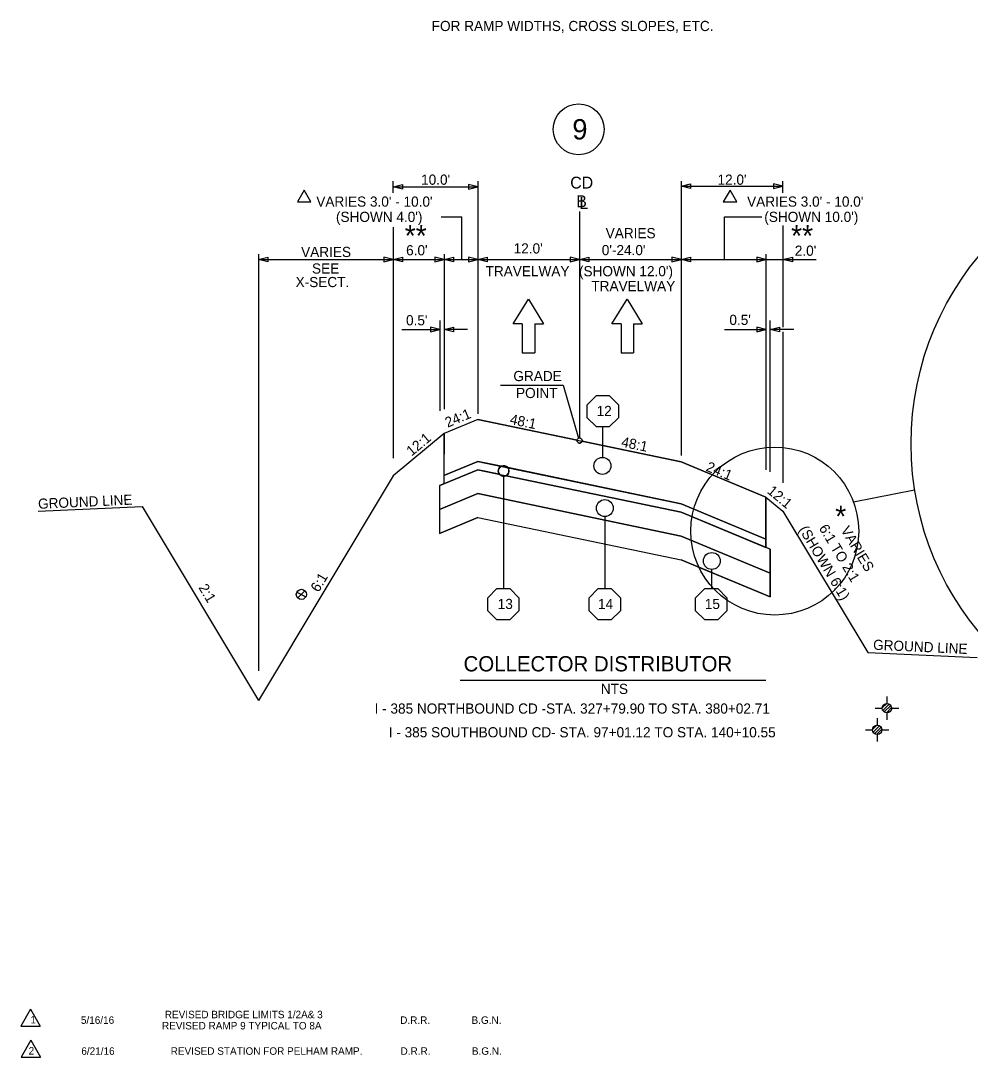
# Model space of a CAD drawing. Extents: x 5017 to 5774, y 4942 to 5266.
# Drawn here: x 5017.3 to 5129.3, y 5018.6 to 5140.9 of the extents above; entities that cross this region are included whole.
import ezdxf

# ---------------------------------------------------------------- set-up
doc = ezdxf.new("R2010")
doc.units = 0
for name, color, linetype in [('Level 20', 7, 'Continuous'), ('Level 25', 7, 'Continuous'), ('NotForConst', 7, 'Continuous'), ('RD_EX_SU_TX_Misc', 7, 'Continuous'), ('RD_QTY_Miscl_1', 7, 'Continuous'), ('RD_QTY_Miscl_2', 7, 'Continuous'), ('RD_QTY_Miscl_3', 7, 'Continuous'), ('RD_QTY_Stab_Agg_3', 7, 'Continuous'), ('RD_SHT_TX', 7, 'Continuous'), ('RD_SHT_Typical', 7, 'Continuous'), ('RD_TX_TypSect', 7, 'Continuous'), ('RD_XS_ExGround', 7, 'Continuous'), ('typical_on', 7, 'Continuous')]:
    doc.layers.add(name, color=color, linetype=linetype)

# ---------------------------------------------------------------- blocks, each defined once
blk = doc.blocks.new('SUE_TFP')
at = {"layer": 'RD_EX_SU_TX_Misc'}
for p, q in [((0, 5.5), (0, 2.22)), ((-2.21, 0.13), (-0.13, 2.21)), ((-1.96, -1.03), (1.03, 1.96)), ((-1.31, -1.79), (1.79, 1.31)), ((-0.3, -2.2), (2.2, 0.3)), ((2.22, 0), (5.53, 0.01)), ((-5.53, -0.01), (-2.22, 0)), ((0, -2.22), (0, -5.5))]:
    blk.add_line(p, q, dxfattribs=at)
blk.add_circle((0, 0), 2.22, dxfattribs=at)

msp = doc.modelspace()

# ---------------------------------------------------------------- linework, layer by layer
at = {"layer": 'Level 20'}
for p, q in [((5075.36, 5105.16), (5077.18, 5108.07)), ((5077.18, 5108.07), (5078.97, 5105.15)), ((5087.01, 5105.16), (5088.83, 5108.07)), ((5088.83, 5108.07), (5090.61, 5105.15)), ((5076.45, 5105.16), (5075.36, 5105.16)), ((5076.45, 5105.16), (5076.45, 5101.76)), ((5077.91, 5105.15), (5078.97, 5105.15)), ((5077.91, 5105.15), (5077.91, 5101.75)), ((5088.1, 5105.16), (5087.01, 5105.16)), ((5088.1, 5105.16), (5088.1, 5101.76)), ((5089.56, 5105.15), (5090.61, 5105.15)), ((5089.56, 5105.15), (5089.56, 5101.75)), ((5076.45, 5101.76), (5077.91, 5101.75)), ((5088.1, 5101.76), (5089.56, 5101.75))]:
    msp.add_line(p, q, dxfattribs=at)
at = {"layer": 'Level 25'}
msp.add_lwpolyline([(5073.89, 5097.92), (5081.29, 5097.92), (5083.09, 5091.66)], dxfattribs=at)
msp.add_circle((5083.1, 5128.12), 3, dxfattribs=at)
at = {"layer": 'RD_QTY_Miscl_1'}
for p, q in [((5071.21, 5088.93), (5067.2, 5087.26)), ((5073.97, 5088.36), (5071.21, 5088.93)), ((5067.19, 5086.28), (5071.19, 5087.95)), ((5071.19, 5087.95), (5073.74, 5087.42)), ((5095.21, 5083.93), (5074.73, 5088.2)), ((5074.55, 5087.25), (5095.21, 5082.94)), ((5105.21, 5079.77), (5095.21, 5083.93)), ((5095.21, 5082.94), (5105.21, 5078.78)), ((5105.21, 5078.78), (5105.21, 5079.77))]:
    msp.add_line(p, q, dxfattribs=at)
msp.add_lwpolyline([(5067.2, 5087.26), (5067.2, 5087.26), (5067.19, 5086.28)], dxfattribs=at)
for start, end in [(116.2833, 217.2732), (299.1906, 40.1805)]:
    msp.add_arc((5074.25, 5087.8), 0.63, start, end, dxfattribs=at)
at = {"layer": 'RD_QTY_Miscl_2'}
for p, q in [((5073.74, 5087.42), (5071.19, 5087.95)), ((5095.21, 5082.94), (5074.55, 5087.25)), ((5066.69, 5086.08), (5066.69, 5083.26)), ((5066.69, 5083.26), (5071.19, 5085.14)), ((5071.19, 5085.14), (5095.21, 5080.13)), ((5095.21, 5080.13), (5105.71, 5075.75)), ((5105.71, 5075.75), (5105.71, 5078.57))]:
    msp.add_line(p, q, dxfattribs=at)
for points in [[(5071.19, 5087.95), (5067.19, 5086.28), (5066.69, 5086.08)], [(5105.71, 5078.57), (5105.21, 5078.78), (5095.21, 5082.94)]]:
    msp.add_lwpolyline(points, dxfattribs=at)
msp.add_circle((5086.19, 5083.43), 1, dxfattribs=at)
msp.add_arc((5074.25, 5087.8), 0.63, 217.2732, 299.1906, dxfattribs=at)
at = {"layer": 'RD_QTY_Miscl_3'}
for p, q in [((5071.19, 5085.14), (5066.69, 5083.26)), ((5095.21, 5080.13), (5071.19, 5085.14)), ((5066.69, 5080.45), (5071.19, 5082.32)), ((5071.19, 5082.32), (5095.21, 5077.32)), ((5105.71, 5075.75), (5095.21, 5080.13)), ((5105.71, 5072.94), (5105.71, 5075.75))]:
    msp.add_line(p, q, dxfattribs=at)
for points in [[(5066.69, 5083.26), (5066.69, 5083.26), (5066.69, 5080.45)], [(5095.21, 5077.32), (5098.76, 5075.84), (5105.71, 5072.94)]]:
    msp.add_lwpolyline(points, dxfattribs=at)
msp.add_circle((5098.82, 5077.19), 1, dxfattribs=at)
at = {"layer": 'RD_QTY_Stab_Agg_3'}
for p, q in [((5071.21, 5093.9), (5067.21, 5092.23)), ((5082.92, 5091.46), (5071.21, 5093.9)), ((5067.21, 5092.23), (5067.2, 5087.26)), ((5085.75, 5090.87), (5083.51, 5091.34)), ((5067.2, 5087.26), (5071.21, 5088.93)), ((5071.21, 5088.93), (5073.97, 5088.36)), ((5105.21, 5084.73), (5095.21, 5088.9)), ((5074.73, 5088.2), (5095.21, 5083.93)), ((5095.21, 5083.93), (5105.21, 5079.77)), ((5105.21, 5079.77), (5105.21, 5084.73))]:
    msp.add_line(p, q, dxfattribs=at)
msp.add_lwpolyline([(5095.21, 5088.9), (5085.96, 5090.83), (5085.75, 5090.87)], dxfattribs=at)
msp.add_circle((5085.9, 5088.41), 1, dxfattribs=at)
for centre, radius, start, end in [((5083.21, 5091.4), 0.3, 168.2319, 348.2319), ((5074.25, 5087.8), 0.63, 40.1805, 116.2833)]:
    msp.add_arc(centre, radius, start, end, dxfattribs=at)
at = {"layer": 'RD_SHT_TX'}
for p, q in [((5018.4, 5024.32), (5017.26, 5022.29)), ((5018.4, 5024.32), (5019.54, 5022.29)), ((5017.26, 5022.29), (5019.54, 5022.29)), ((5018.44, 5020.67), (5017.3, 5018.64)), ((5018.44, 5020.67), (5019.58, 5018.64)), ((5017.3, 5018.64), (5019.58, 5018.64))]:
    msp.add_line(p, q, dxfattribs=at)
at = {"layer": 'RD_SHT_Typical'}
for p, q in [((5071.21, 5093.9), (5067.21, 5092.23)), ((5067.21, 5092.23), (5061.21, 5087.23)), ((5067.19, 5092.23), (5067.19, 5086.28)), ((5067.19, 5087.26), (5071.21, 5088.93)), ((5095.21, 5088.9), (5105.21, 5084.73)), ((5071.19, 5087.95), (5066.69, 5086.07)), ((5071.19, 5087.95), (5095.21, 5082.94)), ((5061.21, 5087.23), (5045.31, 5060.74)), ((5066.69, 5086.08), (5066.69, 5080.45)), ((5071.19, 5085.14), (5066.69, 5083.26)), ((5071.19, 5085.14), (5095.21, 5080.13)), ((5105.21, 5079.77), (5095.21, 5083.93)), ((5105.21, 5084.73), (5107.21, 5083.07)), ((5105.21, 5084.72), (5105.21, 5078.78)), ((5031.58, 5083.63), (5045.31, 5060.74)), ((5105.71, 5078.57), (5095.21, 5082.94)), ((5107.21, 5083.07), (5117.22, 5066.39)), ((5071.19, 5082.32), (5066.69, 5080.45)), ((5071.19, 5082.32), (5095.21, 5077.32)), ((5105.71, 5075.75), (5095.21, 5080.13)), ((5105.71, 5078.57), (5105.71, 5072.94)), ((5105.71, 5072.94), (5095.21, 5077.32))]:
    msp.add_line(p, q, dxfattribs=at)
for points in [[(5071.21, 5093.9), (5085.75, 5090.87)], [(5085.75, 5090.87), (5095.21, 5088.9)], [(5071.21, 5088.93), (5095.21, 5083.93)]]:
    msp.add_lwpolyline(points, dxfattribs=at)
at = {"layer": 'RD_TX_TypSect'}
for p, q in [((5061.21, 5120.61), (5061.21, 5122)), ((5071.21, 5122), (5071.21, 5094.54)), ((5095.21, 5122), (5095.21, 5089.62)), ((5107.21, 5120.61), (5107.21, 5122)), ((5061.21, 5121.33), (5071.21, 5121.33)), ((5095.22, 5121.4), (5107.21, 5121.4)), ((5083.21, 5118.41), (5083.21, 5091.7)), ((5066.86, 5117.81), (5069.3, 5117.81)), ((5069.3, 5112.74), (5069.3, 5117.81)), ((5100.33, 5117.81), (5104.72, 5117.81)), ((5100.33, 5112.74), (5100.33, 5117.81)), ((5061.21, 5116.57), (5061.21, 5089.33)), ((5107.21, 5116.76), (5107.21, 5104.77)), ((5045.31, 5113.39), (5045.31, 5064.22)), ((5067.21, 5113.39), (5067.21, 5095.1)), ((5105.21, 5113.39), (5105.21, 5087.93)), ((5045.31, 5112.77), (5061.21, 5112.77)), ((5061.21, 5112.77), (5067.21, 5112.77)), ((5067.21, 5112.77), (5071.21, 5112.77)), ((5071.21, 5112.77), (5083.22, 5112.77)), ((5083.22, 5112.77), (5095.22, 5112.77)), ((5095.22, 5112.77), (5105.21, 5112.77)), ((5105.21, 5112.77), (5107.21, 5112.77)), ((5107.21, 5112.77), (5111.12, 5112.77)), ((5066.71, 5105.58), (5066.71, 5094.9)), ((5105.71, 5087.72), (5105.71, 5105.58)), ((5062.25, 5104.5), (5066.71, 5104.5)), ((5069.98, 5104.5), (5067.21, 5104.5)), ((5100.33, 5104.5), (5105.21, 5104.5)), ((5108.48, 5104.5), (5105.71, 5104.5)), ((5107.21, 5104.22), (5107.21, 5086.39)), ((5085.96, 5089.4), (5085.96, 5093.01)), ((5074.22, 5087.17), (5074.22, 5073.94)), ((5115.54, 5084.15), (5122.75, 5085.59)), ((5086.18, 5082.43), (5086.18, 5073.94)), ((5098.76, 5076.19), (5098.76, 5073.94)), ((5049.84, 5073.52), (5050.91, 5072.97)), ((5049.96, 5072.83), (5050.79, 5073.67)), ((5069.13, 5063.11), (5105.18, 5063.11))]:
    msp.add_line(p, q, dxfattribs=at)
for points in [[(5096.32, 5121.68), (5096.32, 5121.13), (5095.22, 5121.4)], [(5106.11, 5121.68), (5106.11, 5121.13), (5107.21, 5121.4)], [(5050.71, 5120.95), (5049.91, 5119.57), (5051.51, 5119.57)], [(5062.32, 5121.6), (5062.32, 5121.05), (5061.21, 5121.33)], [(5070.11, 5121.6), (5070.11, 5121.05), (5071.21, 5121.33)], [(5100.97, 5120.95), (5100.17, 5119.57), (5101.77, 5119.57)], [(5046.42, 5113.05), (5046.42, 5112.5), (5045.31, 5112.77)], [(5060.11, 5113.05), (5060.11, 5112.5), (5061.21, 5112.77)], [(5062.32, 5113.05), (5062.32, 5112.5), (5061.21, 5112.77)], [(5066.11, 5113.05), (5066.11, 5112.5), (5067.21, 5112.77)], [(5068.32, 5113.05), (5068.32, 5112.5), (5067.21, 5112.77)], [(5070.11, 5113.05), (5070.11, 5112.5), (5071.21, 5112.77)], [(5072.32, 5113.05), (5072.32, 5112.5), (5071.21, 5112.77)], [(5082.11, 5113.05), (5082.11, 5112.5), (5083.22, 5112.77)], [(5084.32, 5113.05), (5084.32, 5112.5), (5083.22, 5112.77)], [(5094.11, 5113.05), (5094.11, 5112.5), (5095.22, 5112.77)], [(5096.32, 5113.05), (5096.32, 5112.5), (5095.22, 5112.77)], [(5104.11, 5113.05), (5104.11, 5112.5), (5105.21, 5112.77)], [(5108.32, 5113.05), (5108.32, 5112.5), (5107.21, 5112.77)], [(5065.61, 5104.77), (5065.61, 5104.22), (5066.71, 5104.5)], [(5068.32, 5104.77), (5068.32, 5104.22), (5067.21, 5104.5)], [(5104.11, 5104.77), (5104.11, 5104.22), (5105.21, 5104.5)], [(5106.82, 5104.77), (5106.82, 5104.22), (5105.71, 5104.5)]]:
    msp.add_lwpolyline(points, close=True, dxfattribs=at)
for centre, radius in [((5157.11, 5091), 34.78), ((5083.21, 5091.4), 0.3), ((5106.24, 5080.72), 9.91), ((5085.9, 5088.41), 1), ((5074.25, 5087.8), 0.63), ((5086.19, 5083.43), 1), ((5098.82, 5077.19), 1), ((5050.38, 5073.25), 0.6)]:
    msp.add_circle(centre, radius, dxfattribs=at)
at = {"layer": 'RD_XS_ExGround'}
for p, q in [((5019.32, 5083.07), (5031.58, 5083.63)), ((5117.22, 5066.39), (5130.12, 5065.81))]:
    msp.add_line(p, q, dxfattribs=at)
at = {"layer": 'typical_on'}
for points in [[(5087.81, 5095.62), (5087.81, 5094.09), (5086.72, 5093.01), (5085.19, 5093.01), (5084.11, 5094.09), (5084.11, 5095.62), (5085.19, 5096.7), (5086.72, 5096.7)], [(5076.06, 5072.85), (5076.06, 5071.32), (5074.98, 5070.24), (5073.45, 5070.24), (5072.37, 5071.32), (5072.37, 5072.85), (5073.45, 5073.94), (5074.98, 5073.94)], [(5088.03, 5072.85), (5088.03, 5071.32), (5086.94, 5070.24), (5085.41, 5070.24), (5084.33, 5071.32), (5084.33, 5072.85), (5085.41, 5073.94), (5086.94, 5073.94)], [(5100.6, 5072.85), (5100.6, 5071.32), (5099.52, 5070.24), (5097.99, 5070.24), (5096.91, 5071.32), (5096.91, 5072.85), (5097.99, 5073.94), (5099.52, 5073.94)]]:
    msp.add_lwpolyline(points, close=True, dxfattribs=at)

# ---------------------------------------------------------------- block references
at = {"layer": 'NotForConst', "xscale": 0.24999999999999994, "yscale": 0.24999999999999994}
for p in [(5119.49, 5059.82), (5118.34, 5057.26)]:
    msp.add_blockref('SUE_TFP', p, dxfattribs=at)

# ---------------------------------------------------------------- texts
at = {"layer": 'Level 25'}
for s, height, p in [('9', 2.4, (5082.36, 5126.92)), ('CD', 1.4, (5082.11, 5121.13)), ('B', 1.4, (5082.82, 5118.93))]:
    msp.add_text(s, height=height, dxfattribs=at).set_placement(p)
at = {"layer": 'RD_SHT_TX'}
for s, p in [('REVISED BRIDGE LIMITS 1/2A& 3', (5034.26, 5023.24)), ('1', (5018.4, 5022.62)), ('5/16/16', (5024.36, 5022.58)), ('REVISED RAMP 9 TYPICAL TO 8A', (5033.93, 5021.92)), ('D.R.R.', (5062.04, 5022.58)), ('B.G.N.', (5070.46, 5022.58)), ('2', (5018.19, 5018.96)), ('6/21/16', (5024.41, 5018.93)), ('REVISED STATION FOR PELHAM RAMP.', (5034.96, 5018.93)), ('D.R.R.', (5062.08, 5018.93)), ('B.G.N.', (5070.5, 5018.93))]:
    msp.add_text(s, height=0.88, dxfattribs=at).set_placement(p)
at = {"layer": 'RD_TX_TypSect'}
for s, height, p in [('FOR RAMP WIDTHS, CROSS SLOPES, ETC.', 1.2, (5065.76, 5139.71)), ("10.0'", 1.2, (5064.51, 5121.58)), ("12.0'", 1.2, (5099.49, 5121.58)), ("VARIES 3.0' - 10.0'", 1.2, (5052.14, 5118.99)), ('L', 1.4, (5083.19, 5118.73)), ("VARIES 3.0' - 10.0'", 1.2, (5102.98, 5118.99)), ("(SHOWN 4.0')", 1.2, (5054.46, 5117.19)), ("(SHOWN 10.0')", 1.2, (5105.01, 5117.19)), ('**', 2.5, (5062.57, 5114.31)), ('**', 2.5, (5108.17, 5114.31)), ('VARIES', 1.2, (5086.29, 5115.27)), ("6.0'", 1.2, (5062.74, 5113.25)), ("12.0'", 1.2, (5075.43, 5113.47)), ("0'-24.0'", 1.2, (5085.83, 5113.27)), ("2.0'", 1.2, (5108.61, 5113.2)), ('VARIES', 1.2, (5050.35, 5113.05)), ('SEE', 1.2, (5051.63, 5111.1)), ('TRAVELWAY', 1.2, (5072.12, 5110.78)), ("(SHOWN 12.0')", 1.2, (5083.14, 5110.78)), ('X-SECT.', 1.2, (5049.7, 5109.5)), ('TRAVELWAY', 1.2, (5084.6, 5109.02)), ("0.5'", 1.2, (5062.73, 5104.99)), ("0.5'", 1.2, (5100.89, 5105.04)), ('GRADE', 1.2, (5075.4, 5098.41)), ('POINT', 1.2, (5075.71, 5096.41)), ('12', 1.2, (5085.22, 5094.29)), ('*', 2.5, (5113.38, 5081.21)), ('13', 1.2, (5073.55, 5071.52)), ('14', 1.2, (5085.38, 5071.52)), ('15', 1.2, (5097.99, 5071.52)), ('COLLECTOR DISTRIBUTOR', 1.8, (5069.52, 5064.16)), ('NTS', 1.2, (5085.72, 5061.5)), ('I - 385 NORTHBOUND CD -STA. 327+79.90 TO STA. 380+02.71', 1.2, (5059.02, 5059.18)), ('I - 385 SOUTHBOUND CD- STA. 97+01.12 TO STA. 140+10.55', 1.2, (5060.69, 5056.38))]:
    msp.add_text(s, height=height, dxfattribs=at).set_placement(p)
for s, rotation, p in [('24:1', 22.6199, (5067.63, 5092.91)), ('48:1', 348.2317, (5074.91, 5093.37)), ('12:1', 39.8056, (5063.39, 5089.5)), ('48:1', 348.2317, (5088.06, 5090.7)), ('24:1', 337.3801, (5098.04, 5087.86)), ('GROUND LINE', 2.6095, (5019.33, 5083.33)), ('12:1', 320.1944, (5105.27, 5085.28)), ('6:1 TO 2:1', 300.9638, (5111.41, 5081.07)), ('VARIES', 300.9638, (5113.98, 5080.85)), ('(SHOWN 6:1)', 300.9638, (5109.05, 5080.91)), ('6:1', 59.0362, (5052.41, 5073.42)), ('2:1', 300.9638, (5038.2, 5074.05)), ('GROUND LINE', 357.3905, (5117.83, 5066.72))]:
    msp.add_text(s, height=1.2, rotation=rotation, dxfattribs=at).set_placement(p)

doc.saveas('drawing.dxf')
